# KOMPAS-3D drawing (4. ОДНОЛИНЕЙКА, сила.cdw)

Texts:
  ДП.11.213.04.000.00.Э3
  Телятник на 120 голов в СПК колхоз "Дзержинского" Даниловского МР Ярославской обл. Схема электрическая принципиальная
  Электроприёмник
  Условное обозначение
  Тип
  Мощность, кВт
  Номер по плану
  номинальный
  пусковой
  Ток, А
  механизма
  Данные питающей сети
  Обозначение чертежа
  принципиальной схемы
  Марка и сечение
  проводника
  Длина линии, м
  Способ прокладки
  Пусковой
  аппарат
  Тип теплового реле
  Автомат
  Ток расцепителя, А
  Сборные
  шины
  Напряжение, В
  Руст, кВт
  Iрасц, А
  Аппарат
  ввода
  Iном, А
  ВА51-35
  QF1
  ВВГ(4х10)
  от КТП,  ф1
  комплект
  АИР100L4У3
  АИР80В4У3
  Водонагреватель
  ЭВП - 1
  горизонтальный
  наклонный
  Навозоуборочный транспортёр ТСН-160
  ПВ 4(1х1,5)
  ск. l = 20,0 м +
  ВВГ (4х1,5)
  ВА51-31
  QF2
  QF3
  QF4
  ПМЛ 122002
  РТЛ 101404
  РТЛ 100804
  ск.   l = 21,0м
  ск.   l = 26,0м
  Агрегат для приготов-
  ления ЗЦМ АЗМ - 0,8
  УАП-400/0,9
  QF5
  ПМЛ 222002
  электродвигатель
  Электрокалориферная установка СФОЦ - 25/0,5 - И1
  АИР80А4У3
  QF6
  QF7
  QF8
  Резерв
  ВВГ(5х1,5)
  к ЯОУ-8501
  ВВГ (4х6,0)
  ск. l = 12,0м
  ПР85-067;  РУСТ = 58,71 кВт
  ПР-1
  РРАСЧ. = 38,2 кВт; I РАСЧ. = 83,0 А
  Куракин
  ФГОУ ВПО ЯГСХА
  Телятник на 120 голов
  в СПК колхоз "Дзержинского"
  Даниловского МР Ярославской обл.
  Схема электрическая принципиальная
  Шмигель
  Схема управления
  принципиальная однолинейная
  ДП08Ф040200009Э0-
  Королёва
  Орлов
Dimensions and other numbers on the sheet: 1; 2; 3; 4; 5; 6; 7; 6,0; 4,0; 1,5; 9,1; 8,5; 3,52; 59,5; 19,4; 7,0...10,0 А; 2,4...4,0 А; 3,75; 5,7; 39,9; 12,0; 18,2; 7,5; 12,1; 2,75; 15,1; 1 секция ТЭНов; 2 секция ТЭНов; 3 секция ТЭНов; 1,1; 0; 8; 9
